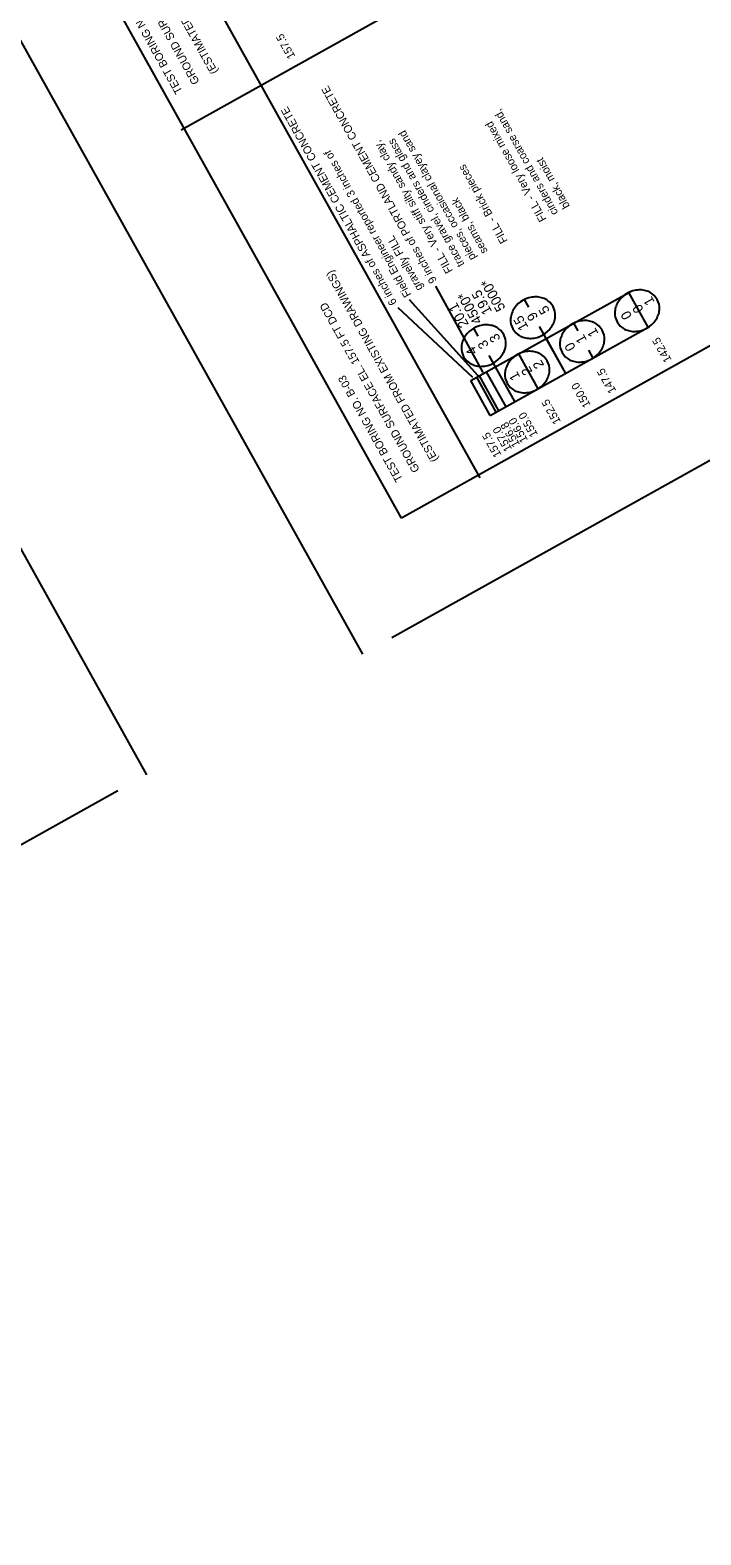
# Model space of a CAD drawing. Extents: x 13482447 to 13495412, y 324533 to 340229.
# Drawn here: x 13494378 to 13494780, y 330757 to 331660 of the extents above; entities that cross this region are included whole.
import ezdxf

# ---------------------------------------------------------------- set-up
doc = ezdxf.new("R2010")
doc.units = 0
for name, color, linetype in [('Default', 7, 'Continuous'), ('DETAIL_TEXT_DIMEN_PR', 7, 'Continuous'), ('Level 1', 7, 'Continuous'), ('TYPICAL_TEXT_DIMEN_PR', 7, 'Continuous')]:
    doc.layers.add(name, color=color, linetype=linetype)

# ---------------------------------------------------------------- blocks, each defined once
blk = doc.blocks.new('DGRFC_BLOW$COUNT$ELLIPSE')
at = {"layer": 'Default'}
blk.add_lwpolyline([(0, -0.0274), (0.0061, -0.0265), (0.0089, -0.0254), (0.0104, -0.0246), (0.0118, -0.0238), (0.0132, -0.0228), (0.0145, -0.0218), (0.0157, -0.0206), (0.0168, -0.0194), (0.0179, -0.018), (0.0189, -0.0167), (0.0198, -0.0152), (0.0206, -0.0137), (0.0213, -0.0122), (0.022, -0.0106), (0.023, -0.0071), (0.0236, -0.0036), (0.0238, 0), (0.0236, 0.0036), (0.023, 0.0071), (0.022, 0.0106), (0.0213, 0.0122), (0.0206, 0.0137), (0.0198, 0.0152), (0.0189, 0.0167), (0.0179, 0.018), (0.0168, 0.0194), (0.0157, 0.0206), (0.0145, 0.0218), (0.0132, 0.0228), (0.0118, 0.0238), (0.0104, 0.0246), (0.0089, 0.0254), (0.0061, 0.0265), (0, 0.0274), (-0.0061, 0.0265), (-0.0089, 0.0254), (-0.0104, 0.0246), (-0.0118, 0.0238), (-0.0132, 0.0228), (-0.0145, 0.0218), (-0.0157, 0.0206), (-0.0168, 0.0194), (-0.0179, 0.018), (-0.0189, 0.0167), (-0.0198, 0.0152), (-0.0206, 0.0137), (-0.0213, 0.0122), (-0.022, 0.0106), (-0.023, 0.0071), (-0.0236, 0.0036), (-0.0238, 0), (-0.0236, -0.0036), (-0.023, -0.0071), (-0.022, -0.0106), (-0.0213, -0.0122), (-0.0206, -0.0137), (-0.0198, -0.0152), (-0.0189, -0.0167), (-0.0179, -0.018), (-0.0168, -0.0194), (-0.0157, -0.0206), (-0.0145, -0.0218), (-0.0132, -0.0228), (-0.0118, -0.0238), (-0.0104, -0.0246), (-0.0089, -0.0254), (-0.0061, -0.0265), (0, -0.0274)], dxfattribs=at)

msp = doc.modelspace()

# ---------------------------------------------------------------- linework, layer by layer
at = {"layer": 'Default'}
for points in [[(13495090.79, 331946.89), (13494468.39, 331599.61)], [(13494642.2, 331449.26), (13494737.85, 331502.51)], [(13494748.68, 331481.25), (13494736.98, 331502.21)], [(13494653.89, 331428.3), (13494749.44, 331481.74)], [(13494699.26, 331453.52), (13494687.57, 331474.48)], [(13494682.7, 331444.44), (13494671, 331465.39)], [(13494663.35, 331433.58), (13494651.66, 331454.54)], [(13494653.89, 331428.3), (13494642.2, 331449.26)], [(13494653.89, 331428.3), (13494642.2, 331449.26)], [(13494657.47, 331430.3), (13494645.77, 331451.26)], [(13494659.05, 331431.18), (13494647.35, 331452.14)]]:
    msp.add_lwpolyline(points, dxfattribs=at)
at = {"layer": 'Level 1'}
for p, q in [((13494577.44, 331285.22), (13493877.74, 332539.22)), ((13494600.6, 331366.85), (13493959.37, 332516.06)), ((13494447.74, 331212.85), (13493748.04, 332466.85)), ((13495330.65, 331774.2), (13494600.6, 331366.85)), ((13495394.81, 331741.29), (13494594.91, 331294.96)), ((13494430.28, 331203.1), (13493630.37, 330756.78))]:
    msp.add_line(p, q, dxfattribs=at)
at = {"layer": 'TYPICAL_TEXT_DIMEN_PR'}
for p, q in [((13494647.89, 331390.95), (13494253.74, 332097.35)), ((13494649.69, 331454.23), (13494621.33, 331506.01)), ((13494739.63, 331497.47), (13494737.03, 331502.12)), ((13494643.48, 331451.13), (13494598.65, 331492.97)), ((13494646.74, 331452.14), (13494605.45, 331497.77)), ((13494677.06, 331493.3), (13494674.47, 331497.95)), ((13494646.73, 331476.03), (13494644.14, 331480.68)), ((13494686.12, 331477.08), (13494683.52, 331481.72)), ((13494699.26, 331453.52), (13494683.52, 331481.72)), ((13494706.64, 331479.07), (13494704.04, 331483.71)), ((13494748.68, 331481.25), (13494746.09, 331485.9)), ((13494655.78, 331459.81), (13494653.19, 331464.45)), ((13494668.7, 331436.66), (13494653.19, 331464.45)), ((13494673.65, 331460.66), (13494671.06, 331465.3)), ((13494715.69, 331462.84), (13494713.1, 331467.49)), ((13494682.7, 331444.44), (13494680.11, 331449.08))]:
    msp.add_line(p, q, dxfattribs=at)

# ---------------------------------------------------------------- block references
at = {"layer": 'Default', "xscale": 503.9370078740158, "yscale": 503.93700787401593, "rotation": 119.16052892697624}
for p in [(13494742.07, 331491.24), (13494742.07, 331491.24), (13494679.51, 331487.07), (13494679.51, 331487.07), (13494709.08, 331472.84), (13494709.08, 331472.84), (13494649.94, 331470.29), (13494649.94, 331470.29), (13494676.09, 331454.43), (13494676.09, 331454.43)]:
    msp.add_blockref('DGRFC_BLOW$COUNT$ELLIPSE', p, dxfattribs=at)

# ---------------------------------------------------------------- texts
at = {"layer": 'Default'}
for s, height, p in [('5000*', 5.952, (13494663.2, 331492.79)), ('4500*', 5.952, (13494649.23, 331484.99)), (' 19.5', 5.952, (13494656.21, 331488.89)), ('1', 5.95, (13494752.77, 331496.44)), ('1', 5.95, (13494752.77, 331496.44)), (' 20.1', 5.952, (13494642.24, 331481.1)), ('9', 5.95, (13494682.84, 331487.2)), ('5', 5.95, (13494689.83, 331491.09)), ('0', 5.95, (13494739.18, 331487.96)), ('0', 5.95, (13494739.18, 331487.96)), ('0', 5.95, (13494746.17, 331491.86)), ('0', 5.95, (13494746.17, 331491.86)), ('15', 5.952, (13494676.99, 331481.27)), ('1', 5.95, (13494719.02, 331477.55)), ('3', 5.95, (13494653.27, 331470.41)), ('3', 5.95, (13494660.26, 331474.31)), ('0', 5.95, (13494705.43, 331469.06)), ('1', 5.95, (13494712.03, 331473.65)), ('4', 5.95, (13494646.29, 331466.52)), ('1', 5.95, (13494672.06, 331451.34)), ('2', 5.95, (13494679.43, 331454.55)), ('2', 5.95, (13494686.41, 331458.45))]:
    msp.add_text(s, height=height, rotation=119.16053, dxfattribs=at).set_placement(p)
at = {"layer": 'DETAIL_TEXT_DIMEN_PR'}
for s, p in [('(ESTIMATED FROM EXISTING DRAWINGS)', (13494490.61, 331634.73)), ('GROUND SURFACE EL. 157.5 FT DCD', (13494479.53, 331628.55)), ('TEST BORING NO. B-03A', (13494469.35, 331622.87)), ('157.5', (13494537.03, 331643.87)), ('9 inches of PORTLAND CEMENT CONCRETE', (13494622, 331509.23)), ('6 inches of ASPHALTIC CEMENT CONCRETE', (13494598.01, 331496.04)), ('cinders and coarse sand, ', (13494694.81, 331550.05)), ('pieces, occasional clayey sand ', (13494645.56, 331522.98)), ('FILL - Very loose mixed ', (13494687.82, 331546.16)), ('FILL - Very stiff silty sandy clay, ', (13494631.59, 331515.18)), ('trace gravel, cinders and glass ', (13494638.57, 331519.08)), ('Field Engineer reported 3 inches of ', (13494606.63, 331500.85)), ('black, moist', (13494701.8, 331553.95)), ('FILL - Brick pieces', (13494664.45, 331533.11)), ('seams, black', (13494652.54, 331526.87)), ('gravelly FILL', (13494613.61, 331504.75)), ('(ESTIMATED FROM EXISTING DRAWINGS)', (13494622.82, 331401.98)), ('GROUND SURFACE EL. 157.5 FT DCD', (13494611.74, 331395.79)), ('142.5', (13494762.87, 331461.74)), ('147.5', (13494729.66, 331443.21)), ('TEST BORING NO. B-03', (13494601.56, 331390.11)), ('150.0', (13494714.28, 331434.63)), ('152.5', (13494696.44, 331424.67)), ('156.0', (13494676.6, 331413.61)), ('155.0', (13494682.6, 331416.95)), ('157.5', (13494660.76, 331404.77)), ('157.0', (13494667.06, 331408.29)), ('156.8', (13494671.83, 331410.95))]:
    msp.add_text(s, height=4.8, rotation=119.16053, dxfattribs=at).set_placement(p)

doc.saveas('drawing.dxf')
